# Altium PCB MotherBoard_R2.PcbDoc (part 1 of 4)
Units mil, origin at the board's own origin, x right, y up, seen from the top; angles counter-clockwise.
Board outline 9500 x 4600 mil, 4 copper layers (Top Layer, Power Layer, GND Layer, Bottom Layer), stack 61.6 mil thick; 206 components, 289 nets, 935 pads, 328 vias.
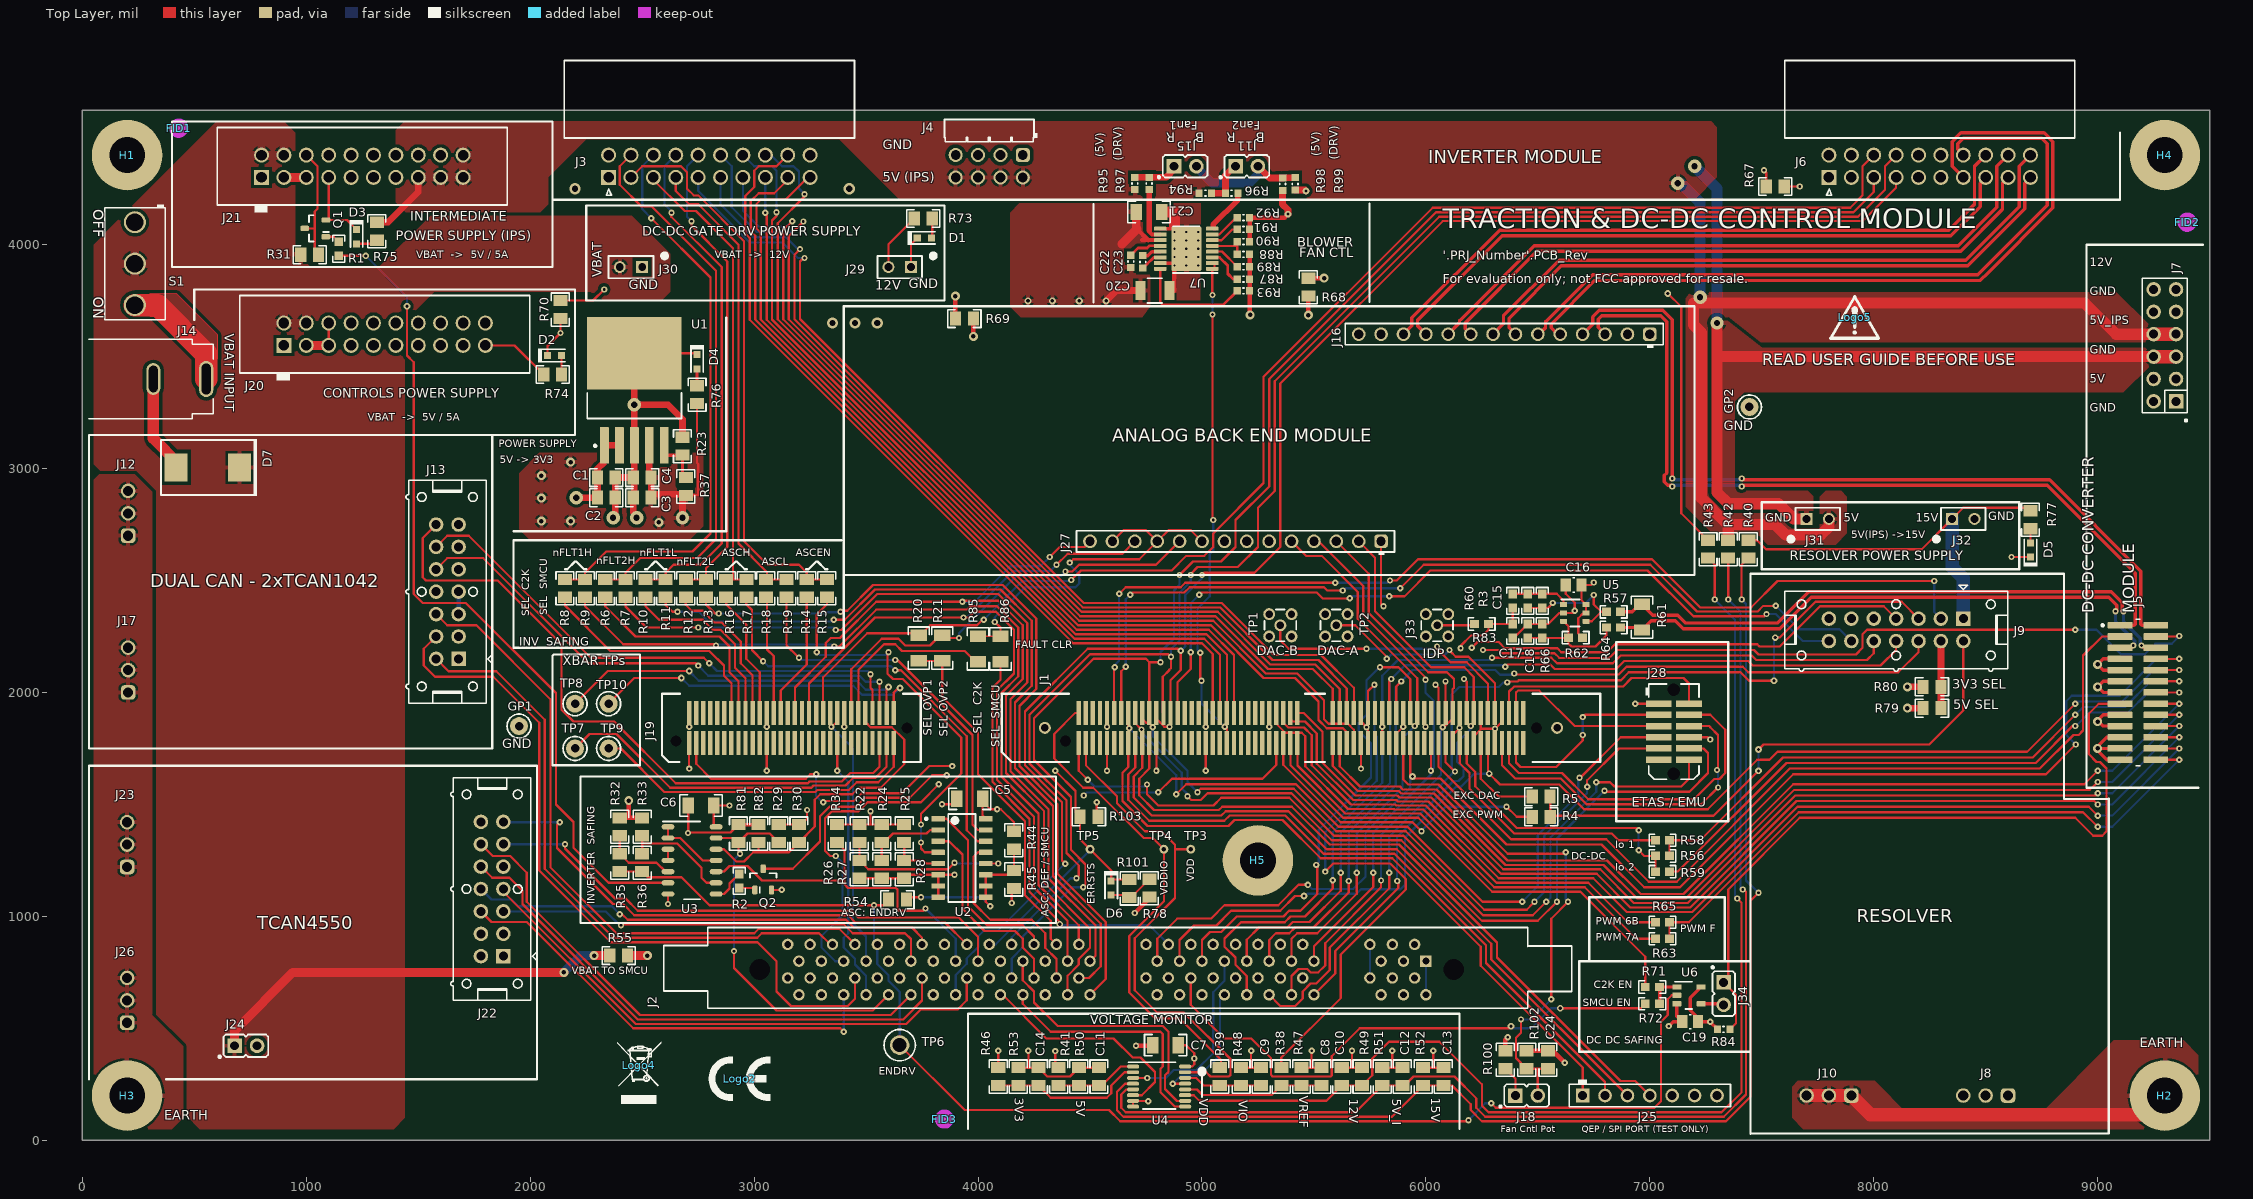
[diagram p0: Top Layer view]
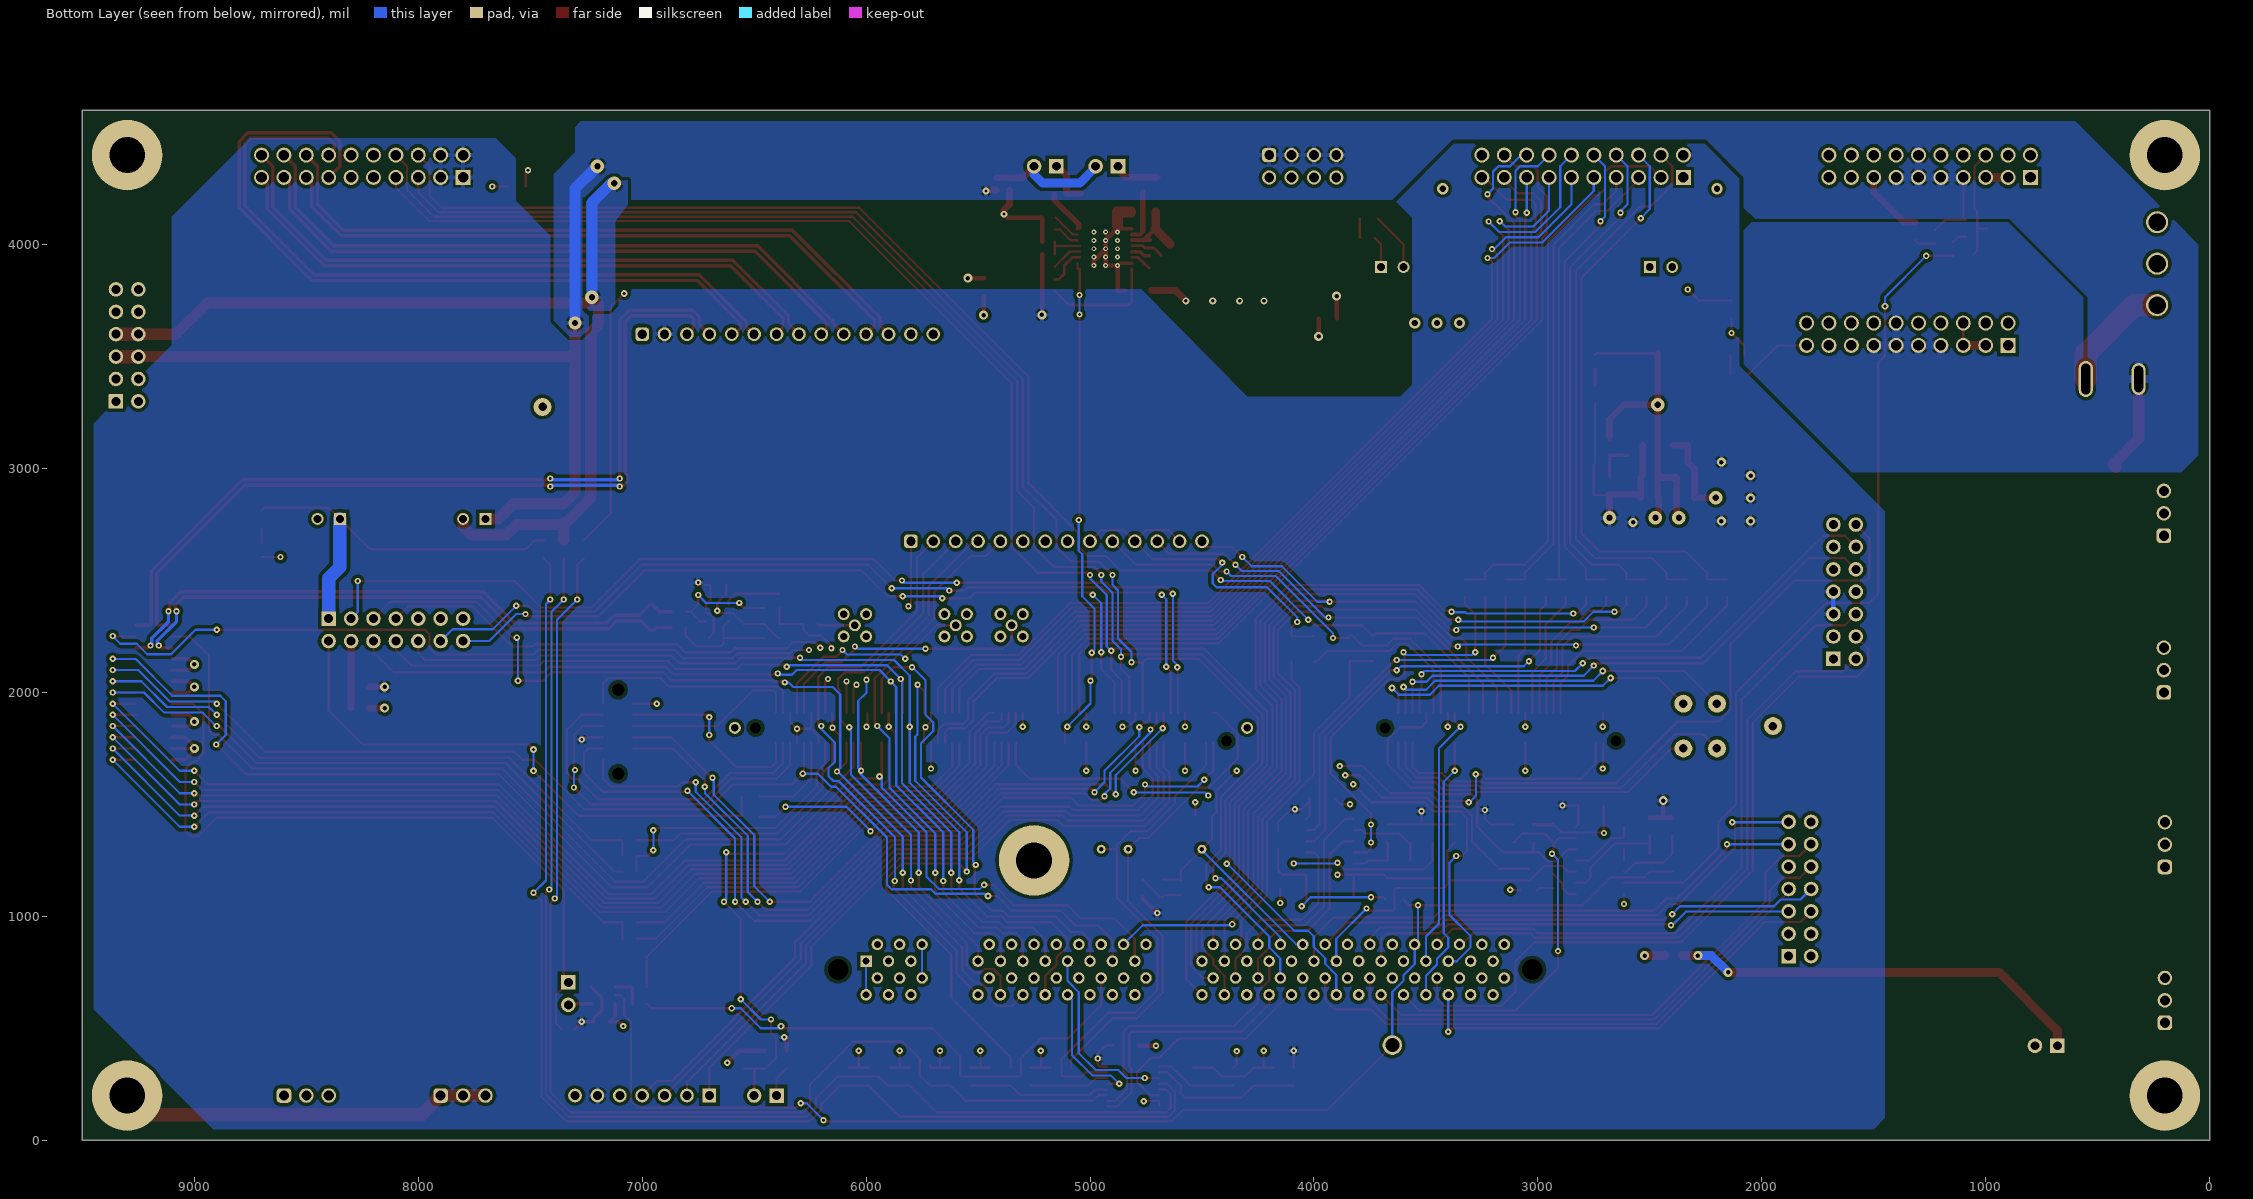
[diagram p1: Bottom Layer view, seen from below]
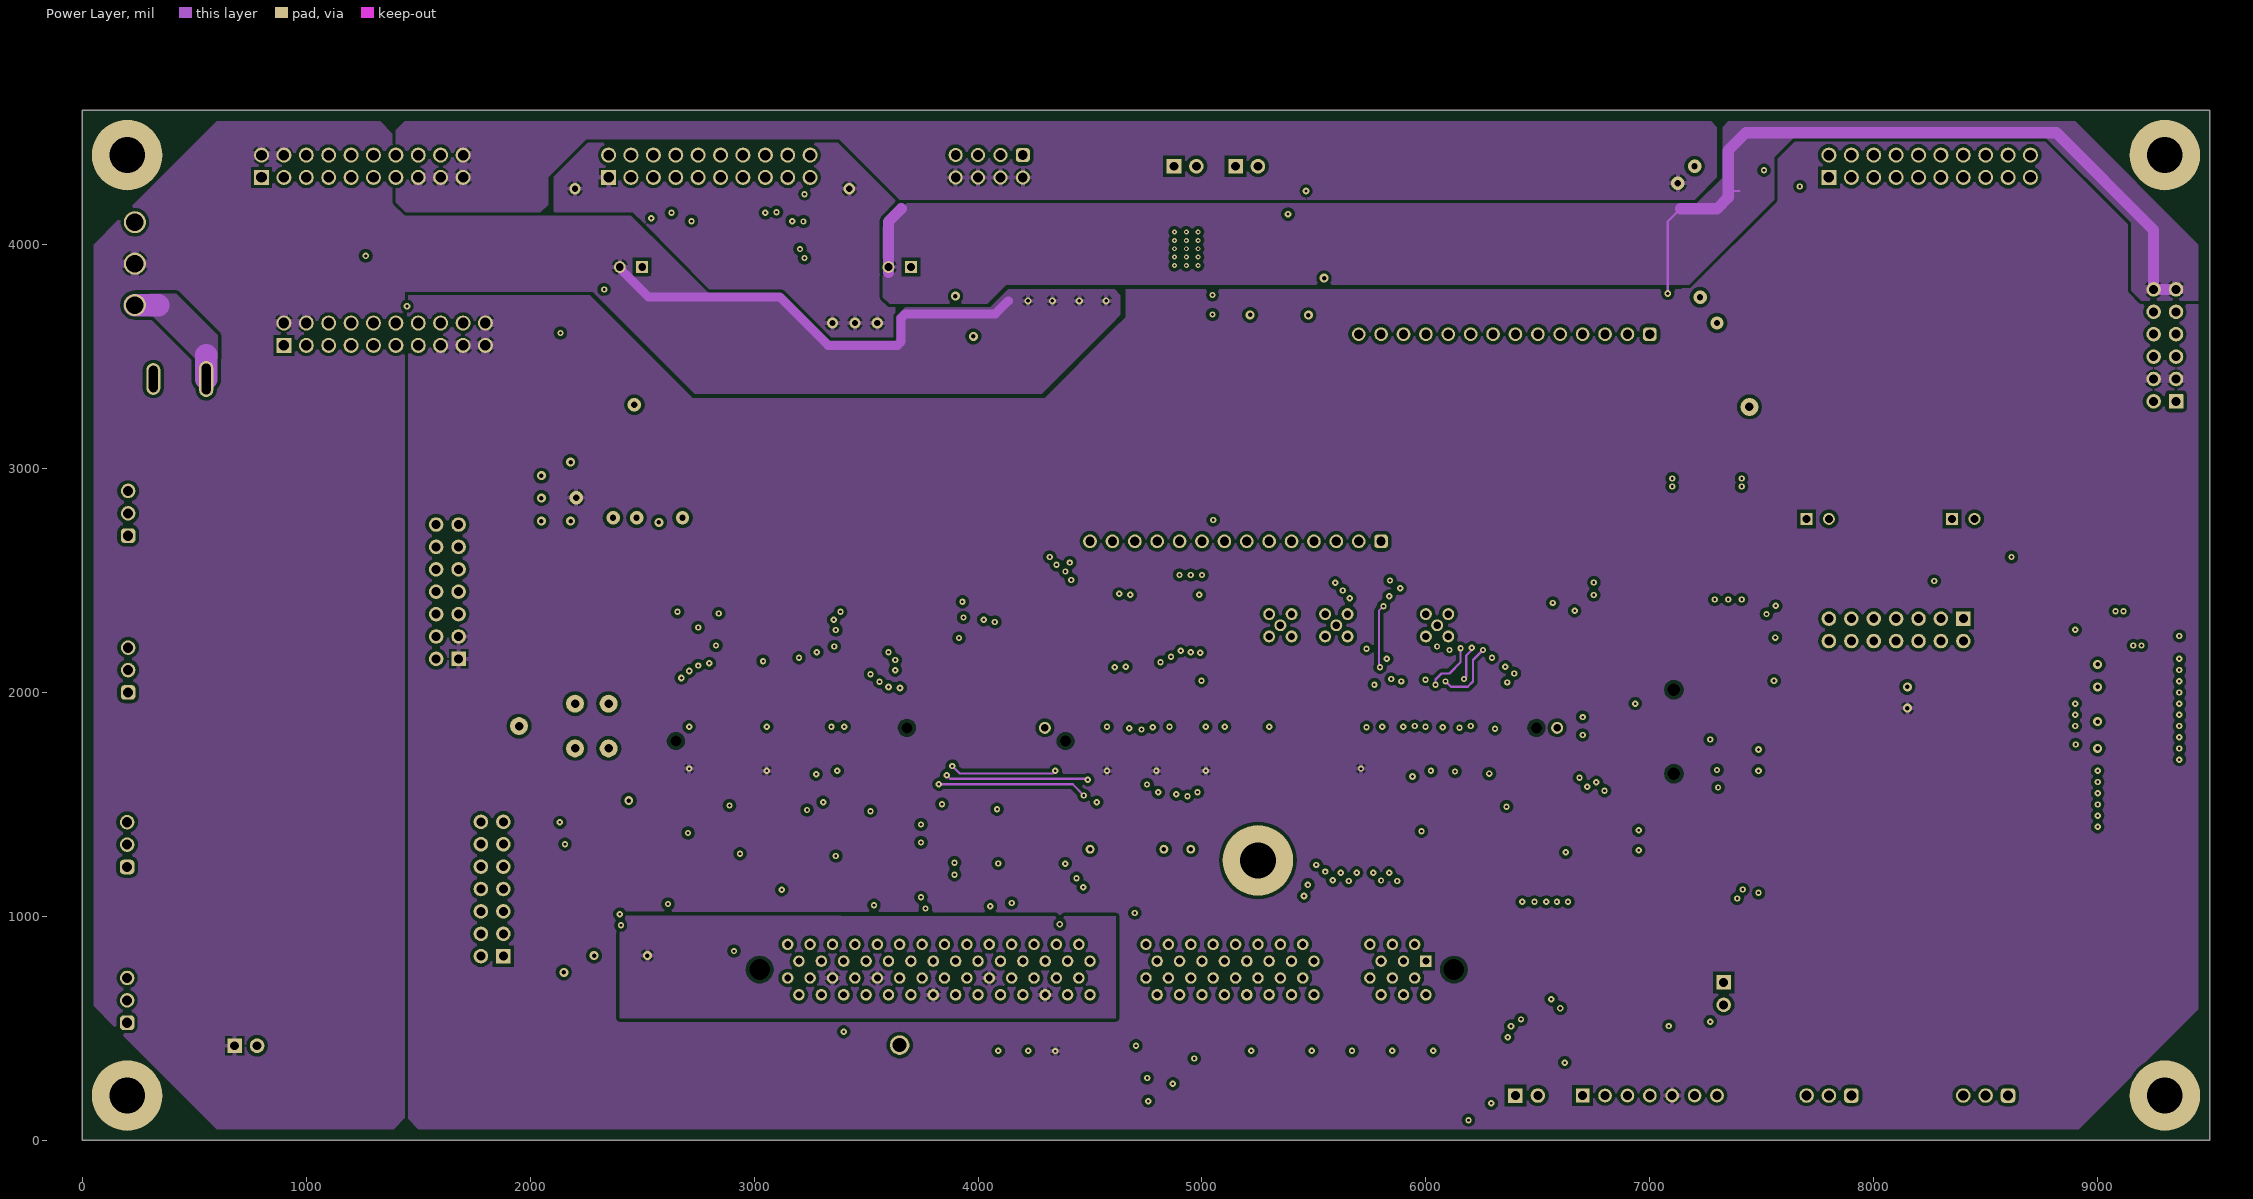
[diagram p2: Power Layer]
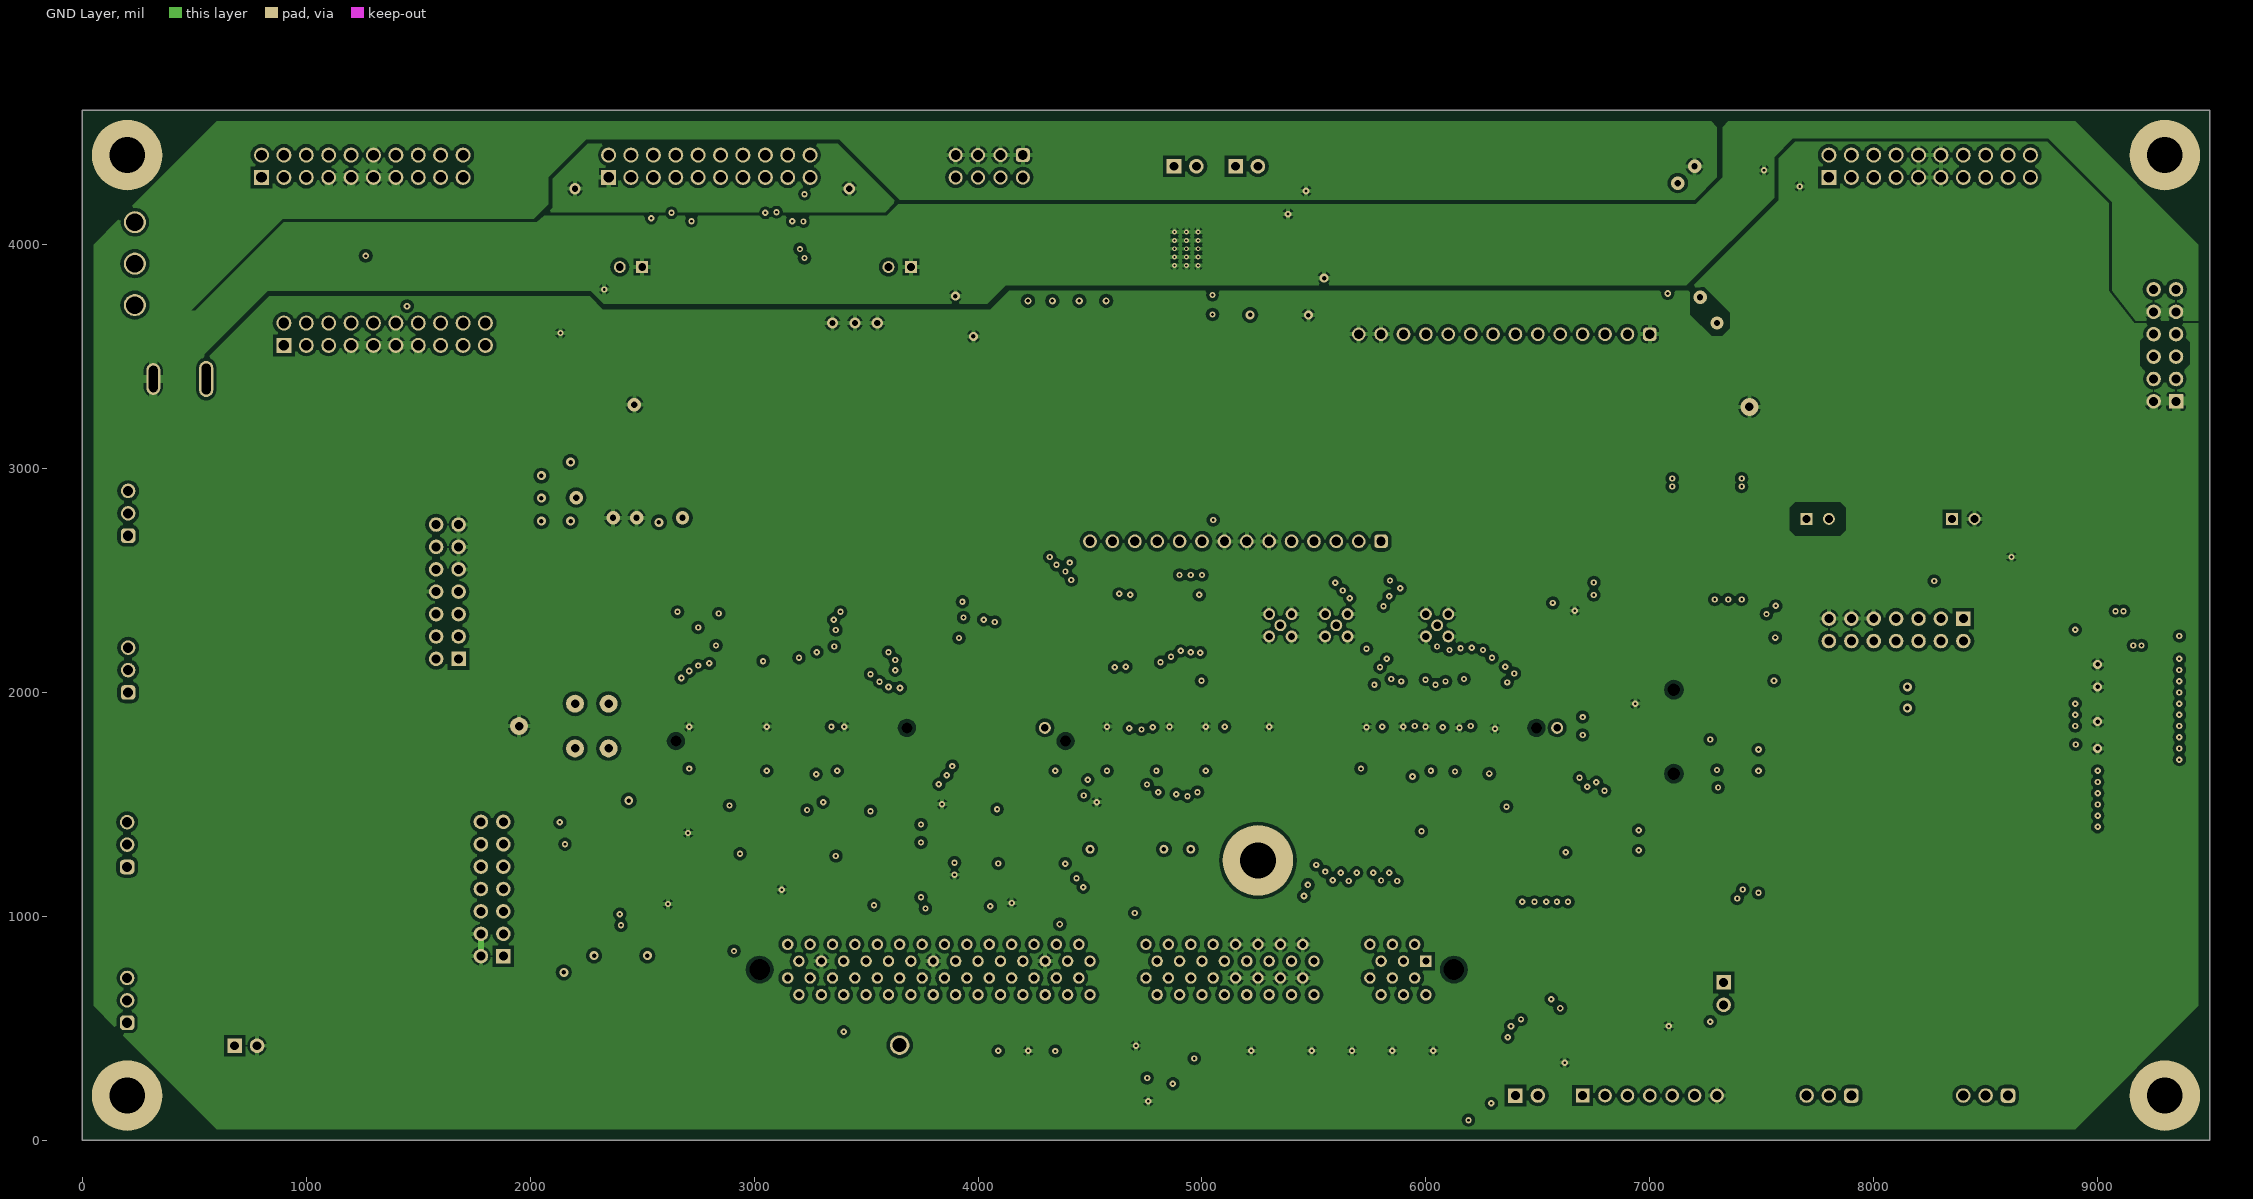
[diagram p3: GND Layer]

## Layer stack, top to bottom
Top Solder: solder mask 0.4, Solder Resist, Dk 3.5
Top Layer: signal copper 1.4
Dielectric 1: prepreg 8, FR-4, Dk 4.2
Power Layer: signal copper 1.4
Dielectric 2: core 40, FR-4, Dk 4.2
GND Layer: signal copper 1.4
Dielectric 3: prepreg 8, FR-4, Dk 4.2
Bottom Layer: signal copper 1.4
Bottom Solder: solder mask 0.4, Solder Resist, Dk 3.5

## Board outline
0,0 9500,0 9500,4600 0,4600

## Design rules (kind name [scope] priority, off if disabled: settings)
AcuteAngle [All] p1: minimum=4.50000000000000E+0001 checktracksonly=FALSE
AssemblyTestPointUsage [All] p1: valid=2
BoardOutlineClearance BoardOutlineClearance_MountingHoles [OnCopper and InComponentClass('Mounting Holes')] p1: gap=39.37 ignorepadtopadclearanceinfootprint=FALSE
BoardOutlineClearance BoardOutlineClearance_Poly [OnCopper and IsPoly] p2: gap=25 ignorepadtopadclearanceinfootprint=FALSE
BoardOutlineClearance [OnCopper and Not InComponentClass('Logo') and not InComponentClass('FiducialMark') and not InRegion(1000,500,4000,800) and not InPoly] p3: gap=75 ignorepadtopadclearanceinfootprint=FALSE
Clearance Clearance_New [HasFootprint('YJM0003A')] p1: gap=6 ignorepadtopadclearanceinfootprint=TRUE
Clearance Clearance_Keepouts [((IsTrack Or IsArc) And Not InPoly) And IsFree and IsKeepOut vs ((IsTrack Or IsArc) And Not InPoly) And IsFree and IsKeepOut] p2: gap=0 ignorepadtopadclearanceinfootprint=FALSE
Clearance Clearance_Poly [InPolygon] p3: gap=15 ignorepadtopadclearanceinfootprint=TRUE
Clearance Clearance_FiducialMark [IsKeepOut and InComponentClass('FiducialMark') vs IsPad and InComponentClass('FiducialMark')] p4: gap=0 ignorepadtopadclearanceinfootprint=FALSE
Clearance [All] p5: gap=7.87 ignorepadtopadclearanceinfootprint=TRUE
ComponentClearance ComponentClearance_MountingHoles_FiducialMarks [InComponentClass('Mounting Holes') vs InComponentClass('FiducialMark')] p1: gap=50 collisioncheckmode=3 verticalgap=10 showdistances=FALSE
ComponentClearance ComponentClearance_Shunt [InComponentClass('Header') vs InComponentClass('Shunt')] p2: gap=0 collisioncheckmode=3 verticalgap=0 showdistances=FALSE
ComponentClearance ComponentClearance_Logo [InComponentClass('Logo')] p3: gap=50 collisioncheckmode=3 verticalgap=10 showdistances=FALSE
ComponentClearance ComponentClearance_ScrewToNut [(HasFootprint('NY PMS 440 0025 PH')) vs (HasFootprint('Keystone_1902C'))] p4: gap=5 collisioncheckmode=3 verticalgap=10 showdistances=FALSE
ComponentClearance ComponentClearance_MountingHoles [InComponentClass('Mounting Holes')] p5: gap=100 collisioncheckmode=3 verticalgap=100000 showdistances=FALSE
ComponentClearance ComponentClearance_SmallPassives [HasFootprint('0201*') or HasFootprint('0402*') or HasFootprint('0508') or HasFootprint('0603*') or HasFootprint('0612') or HasFootprint('0805*') or HasFootprint('0815*') or HasFootprint('0830*') or HasFootprint('1206*') or HasFootprint('1210*') or HasFootprint('1808*') or HasFootprint('1812*') or HasFootprint('1825*') or HasFootprint('2010*') or HasFootprint('2220*') or HasFootprint('2225*') or HasFootprint('2512*') or HasFootprint('2728*') or HasFootprint('3518*') vs HasFootprint('0201*') or HasFootprint('0402*') or HasFootprint('0508') or HasFootprint('0603*') or HasFootprint('0612') or HasFootprint('0805*') or HasFootprint('0815*') or HasFootprint('0830*') or HasFootprint('1206*') or HasFootprint('1210*') or HasFootprint('1808*') or HasFootprint('1812*') or HasFootprint('1825*') or HasFootprint('2010*') or HasFootprint('2220*') or HasFootprint('2225*') or HasFootprint('2512*') or HasFootprint('2728*') or HasFootprint('3518*')] p6: gap=14.96 collisioncheckmode=3 verticalgap=10 showdistances=FALSE
ComponentClearance ComponentClearance_THtoSMT [IsThruComponent vs IsSMTComponent] p7: gap=40 collisioncheckmode=3 verticalgap=30 showdistances=FALSE
ComponentClearance ComponentClearance_THtoTH [IsThruComponent vs IsThruComponent] p8: gap=30 collisioncheckmode=3 verticalgap=30 showdistances=FALSE
ComponentClearance [All] p9: gap=30 collisioncheckmode=3 verticalgap=10 showdistances=FALSE
DiffPairsRouting [All] p1: maxlimit=100 minlimit=10 mostfreqgap=10 toplayer_minwidth=15 toplayer_maxwidth=15 toplayer_prefwidth=15 midlayer1_minwidth=15 midlayer1_maxwidth=15 midlayer1_prefwidth=15 midlayer2_minwidth=15 midlayer2_maxwidth=15 midlayer2_prefwidth=15 bottomlayer_minwidth=15 bottomlayer_maxwidth=15 bottomlayer_prefwidth=15 maxuncoupledlength=1000
FabricationTestPointUsage TestPointUsage [All] p1: valid=2 allowmultiple=FALSE
FabricationTestpoint Testpoint [All] p1: side=3 testpointundercomponent=TRUE minsize=40 maxsize=100 preferedsize=60 minholesize=0 maxholesize=40 preferedholesize=32 testpointgrid=1 allowsidetop=TRUE allowsidebottom=TRUE usegrid=TRUE gridtolerance=0.01
FanoutControl Fanout_LCC [IsLCC] p1: bgadir=Out bgaviamode=Centered fanoutstyle=Auto fanoutdirection=Alternating viagrid=1 // Fanout_LCC (Default Rule)
FanoutControl Fanout_BGA [IsBGA] p2: bgadir=Out bgaviamode=Centered fanoutstyle=Auto fanoutdirection=Alternating viagrid=1 // Fanout_BGA (Default Rule)
FanoutControl Fanout_Default [All] p4: bgadir=Out bgaviamode=Centered fanoutstyle=Auto fanoutdirection=Alternating viagrid=1 // Fanout_Default (Default Rule)
FanoutControl Fanout_Small [(CompPinCount < 5)] p5: bgadir=Out bgaviamode=Centered fanoutstyle=Auto fanoutdirection=OutThenIn viagrid=1 // Fanout_Small (Default Rule)
Height [All] p1: minheight=0 maxheight=2000 prefheight=500
HoleSize [All] p1: absolutevalues=TRUE maxlimit=251 minlimit=7.87 maxpercent=80.000 minpercent=20.000
MinimumAnnularRing MinimumAnnularRing_ThermalPadVias [IsVia and InAnyComponent] p1: minimumring=5.91
MinimumAnnularRing [All] p2: minimumring=7.87
MinimumSolderMaskSliver MinimumSolderMaskSliver_Logo [InComponentClass('Logo') vs InComponentClass('Logo')] p1: minsoldermaskwidth=0.7
MinimumSolderMaskSliver [All] p2: minsoldermaskwidth=3.94
PlaneClearance [All] p1: clearance=12
PlaneConnect [All] p1: planeconnectstyle=Relief reliefexpansion=10 reliefentries=4 reliefconductorwidth=25 reliefairgap=10
PolygonConnect [InComponentClass('PowerTerminal')] p1: connectstyle=Relief reliefconductorwidth=40 reliefentries=4 polygonreliefangle="90 Angle" airgapwidth=10
PolygonConnect PolygonConnect_1 [Not InComponentClass('PowerTerminal')] p2: connectstyle=Relief reliefconductorwidth=20 reliefentries=4 polygonreliefangle="90 Angle" airgapwidth=10
RoutingVias ThermalPadVias [IsVia and InAnyComponent] p1: holewidth=7.87 width=19.68 viastyle="Through Hole" minholewidth=7.87 minwidth=19.68 maxholewidth=12.99 maxwidth=23.62
RoutingVias [All] p2: holewidth=16 width=34 viastyle="Through Hole" minholewidth=7.87 minwidth=26 maxholewidth=40 maxwidth=65
SilkToBoardRegionClearance [Not ((IsComment or IsDesignator) And (Hide <> 'False')) and not InRegion(1000,500,4000,800)] p1:
SilkToSilkClearance SilkToSilkClearance_Pb-FreeLogo [(HasFootprint('Pb-Free_Overlay_Medium') OR HasFootprint('Pb-Free_Overlay_Small')) vs (HasFootprint('Pb-Free_Overlay_Medium') OR HasFootprint('Pb-Free_Overlay_Small'))] p1: silktosilkclearance=0
SilkToSilkClearance [All] p2: silktosilkclearance=3.94
SilkToSolderMaskClearance SilkToComponentPadClearance [(IsPad or IsFill or IsRegion) and InAnycomponent] p1: minsilkscreentomaskgap=5 clearancetoexposedcopper=TRUE
SilkToSolderMaskClearance "Silk to Solder Mask Opening" [All] p2: minsilkscreentomaskgap=3.94 clearancetoexposedcopper=FALSE
SolderMaskExpansion [All] p1: expansion=1.97
UnRoutedNet [All] p1: checkbadconnections=TRUE
Width [All] p1: maxlimit=100 minlimit=6 preferedwidth=10 checkconnectedcopper=TRUE
12 further rules are at their usual default settings.

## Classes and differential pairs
component class PowerTerminal: J7 J14 J20 J21 S1
component class ChildBoardDC-DC_r2: C15 C16 C17 C18 C19 J5 J7 J33 J34 R3 R56 R57 R58 R59 R60 R61 R62 R63 R64 R65 R66 R71 R72 R83 R84 U5 U6
component class MotherBoard_r2: d GP1 GP2 J1 J2 J19 TP1 TP2 TP3 TP4 TP5 TP6 TP7 TP8 TP9 TP10
component class powerSupplyAndMontior_r1: C1 C2 C3 C4 C6 C7 C8 C9 C10 C11 C12 C13 C14 D1 D2 D3 D4 D5 D6 D7 J14 J20 J21 J29 J30 J31 J32 Q1 Q2 R1 R2 R23 R29 R30 R31 R32 R33 R34 R35 R36 R37 R38 R39 R40 R41 R42 R43 R46 R47 R48 R49 R50 R51 R52 R53 R55 R67 R68 R69 R70 R73 R74 R75 R76 R77 R78 R81 R82 R101 R103 S1 U1 U3 U4
component class ChildBoardMotor_r2: C5 C20 C21 C22 C23 C24 J3 J4 J6 J8 J9 J10 J11 J15 J16 J18 J25 J27 R4 R5 R6 R7 R8 R9 R10 R11 R12 R13 R14 R15 R16 R17 R18 R19 R20 R21 R22 R24 R25 R26 R27 R28 R44 R45 R54 R79 R80 R85 R86 R87 R88 R89 R90 R91 R92 R93 R94 R95 R96 R97 R98 R99 R100 R102 U2 U7
component class ChildBoardComms_r3: J12 J13 J17 J22 J23 J24 J26 J28
component class Header: J4 J8 J10 J11 J12 J15 J17 J18 J23 J24 J26 J29 J30 J31 J32 J34
component class "Mounting Holes": H1 H2 H3 H4 H5
component class Hardware: FID1 FID2 FID3 H1 H2 H3 H4 H5 Logo2 Logo3 Logo4 Logo5 ZZ1 ZZ2 ZZ3 ZZ4
component class FiducialMark: FID1 FID2 FID3
component class AssemblyNote: ZZ1 ZZ2 ZZ3 ZZ4
differential pair CT: +CT_P -CT_N
differential pair Vdc2: +Vdc2_P -Vdc2_N
differential pair Ia: +Ia_P -Ia_N
differential pair Vdc: +Vdc_P -Vdc_N
differential pair Ic: +Ic_P -Ic_N
differential pair Ib: +Ib_P -Ib_N

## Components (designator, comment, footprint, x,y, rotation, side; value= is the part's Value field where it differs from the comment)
C1 "C2012X7R2A104K125AA" 0805_HV 2340,2960 r0 top value=0.1uF
C2 "GRM21BR61C106KE15K" 0805_HV 2340,2870 r0 top value=10uF
C3 "GRM21BR61C106KE15K" 0805_HV 2500,2870 r0 top value=10uF
C4 "C2012X7R2A104K125AA" 0805_HV 2500,2960 r180 top value=0.1uF
C5 "1206YC104KAT2A" 1206 3962.91,1525 r180 top value=0.1uF
C6 "1206YC104KAT2A" 1206 2762.91,1495 r0 top value=0.1uF
C7 "1206YC104KAT2A" 1206 4837.91,425 r180 top value=0.1uF
C8 "GRM21BR61C106KE15K" 0805_HV 5534.41,284.57 r270 top value=10uF
C9 "GRM21BR61C106KE15K" 0805_HV 5264.41,284.57 r270 top value=10uF
C10 "GRM21BR61C106KE15K" 0805_HV 5624.41,284.57 r270 top value=10uF
C11 "GRM21BR61C106KE15K" 0805_HV 4540,284.57 r270 top value=10uF
C12 "GRM21BR61C106KE15K" 0805_HV 5895,284.57 r270 top value=10uF
C13 "GRM21BR61C106KE15K" 0805_HV 6077.8,284.57 r270 top value=10uF
C14 "GRM21BR61C106KE15K" 0805_HV 4270,284.57 r270 top value=10uF
C15 "GCM188R71H224KA64D" 0603 6520,2408.9 r270 top value=0.22uF
C16 "CEU4J2X7R1H104K125AE" 0805_150 6660,2480 r180 top value=0.1uF
C17 "GCM188R71H224KA64D" 0603 6388.23,2274.5 r270 top value=0.22uF
C18 "GCM188R71H224KA64D" 0603 6455,2274.5 r90 top value=0.22uF
C19 "CEU4J2X7R1H104K125AE" 0805_150 7180,530 r180 top value=0.1uF
C20 "UMJ325KB7106MMHP" 1210_280 4790,3795 r0 top value=10uF
C21 "GRM319R71H104KA01D" 1206 4763.63,4146.03 r0 top value=0.1uF
C22 "885012206095" 0603L 4682.3,3925 r90 top value=0.1uF
C23 "885012206091" 0603L 4736,3923 r270 top value=0.022uF
C24 "SR0805X7R104K1NT95(F)#M123A" 0805_HV 6545,360 r270 top value=0.1uF
D1 "150060GS75000" WL-SMCW_GREEN 3760,4030 r0 top value=Green
D2 "150060GS75000" WL-SMCW_GREEN 2108.5,3505 r0 top value=Green
D3 "150060GS75000" WL-SMCW_GREEN 1225,4035.2 r270 top value=Green
D4 "150060GS75000" WL-SMCW_GREEN 2745,3476.86 r270 top value=Green
D5 "150060GS75000" WL-SMCW_GREEN 8700,2636.5 r90 top value=Green
D6 "150060RS75000" WL-SMCW_RED 4594.67,1127 r270 top value=Red
D7 "S10AL-TP" SMC_265 560,3005 r180 top value=50V
FID1 "Fiducial" Fiducial10-20 430.84,4520 r0 top
FID2 "Fiducial" Fiducial10-20 9400,4100 r0 top
FID3 "Fiducial" Fiducial10-20 3850,95 r0 top
GP1 "TESTPOINT" TESTPOINT 1950,1850 r0 top
GP2 "TESTPOINT" TESTPOINT 7445,3275 r0 top
H1 "NY PMS 440 0025 PH" "NY PMS 440 0025 PH"#1 200,4400 r0 top locked
H2 "NY PMS 440 0025 PH" "NY PMS 440 0025 PH"#1 9300,200 r0 top locked
H3 "NY PMS 440 0025 PH" "NY PMS 440 0025 PH"#2 200,225 r0 top locked
H4 "NY PMS 440 0025 PH" "NY PMS 440 0025 PH"#1 9300,4400 r0 top locked
H5 "NY PMS 440 0025 PH" "NY PMS 440 0025 PH"#3 5250,1240 r0 top locked
J1 "HSEC8-160-01-L-DV-A-BL" controlCARD-120HSEC 5514.69,1842.8 r180 top
J2 "TMDSDIM100CON5PK" TI_TMDSDIM100CON5PK 4623.7,767.4 r180 top
J3 "SBH11-PBPC-D10-RA-BK" Sullins_SBH11-xxxC-D10-RA 2800,4555.12 r90 top
J4 "61300821021" Wurth_61300821021 4050,4350 r270 top
J5 "FTSH-113-01-F-DV-K" FP-FTSH-113-01-F-DV-K_HDR26-MFG 9180.12,2000 r270 top
J6 "SBH11-PBPC-D10-RA-BK" Sullins_SBH11-xxxC-D10-RA 8250,4555.12 r90 top
J7 "TSW-106-07-G-D" TSW-106-07-G-D 9300,3550 r90 top
J8 "61300311121" WURTH_61300311121 8499.66,200 r180 top
J9 "SBH11-PBPC-D07-ST-BK" CONN_SBH11-PBPC-D07-ST-BK 8100,2279.7 r180 top
J10 "61300311121" WURTH_61300311121 7800,200 r180 top
J11 "PBC02SAAN" Sullins_PBC02SAAN 5200,4350 r90 top
J12 "61300311121" WURTH_61300311121 204.36,2800.01 r90 top
J13 "SBH11-PBPC-D07-ST-BK" CONN_SBH11-PBPC-D07-ST-BK 1629.98,2450 r90 top
J14 "PJ-037AH" CUI_PJ-037AH 435,3400 r270 top
J15 "PBC02SAAN" Sullins_PBC02SAAN 4925,4350 r90 top
J16 "SSW-114-01-G-S" Samtec_SSW-114-01-x-S 6350,3600 r180 top
J17 "61300311121" WURTH_61300311121 204.36,2100 r90 top
J18 "PBC02SAAN" Sullins_PBC02SAAN 6450,200 r90 top
J19 "HSEC8-130-01-L-DV-A" controlCARD-180HSEC-60pinAddon 3166.31,1841.93 r180 top
J20 "SBH11-PBPC-D10-ST-BK" Sullins_SBH11-xxxC-D10-ST 1350,3600 r90 top
J21 "SBH11-PBPC-D10-ST-BK" Sullins_SBH11-xxxC-D10-ST 1250,4350 r90 top
J22 "SBH11-PBPC-D07-ST-BK" CONN_SBH11-PBPC-D07-ST-BK 1829.98,1122.3 r90 top
J23 "61300311121" WURTH_61300311121 200,1320.59 r90 top
J24 "PBC02SAAN" Sullins_PBC02SAAN 729.98,422.3 r90 top
J25 "PPPC071LFBN-RC" Sullins_xPxC071LFBN 7000,200 r0 top
J26 "61300311121" WURTH_61300311121 200,625 r90 top
J27 "SSW-114-01-G-S" Samtec_SSW-114-01-x-S 5150,2675 r180 top
J28 "TFM-106-02-S-D-A" Samtec_TFM-106-02-x-D-A 7107.48,1825 r0 top
J29 "5-534206-1" CONN_534206-1 3650,3900 r180 top
J30 "5-534206-1" CONN_534206-1 2450,3900 r180 top
J31 "5-534206-1" CONN_534206-1 7750,2775 r0 top
J32 "5-534206-1" CONN_534206-1 8400,2775 r0 top
J33 "734151471" Molex_0734151471 6050,2300 r0 top
J34 "PBC02SAAN" Sullins_PBC02SAAN 7330,655 r0 top
Logo2 "CE Mark" CE_Mark_5mm 2935,275 r0 top
Logo3 "FCC disclaimer" FCC_disclaimer 12010,4440 r0 top
Logo4 "WEEE logo" WEEE_Minimum 2485,335 r0 top
Logo5 "CAUTION.  READ USER GUIDE BEFORE USE" IEC_Caution_Small 7915,3675 r0 top
Q1 "DMN3053L-7" SOT-23 1040.1,4072.6 r180 top value=30V
Q2 "DMN3053L-7" SOT-23 3040.4,1165.24 r90 top value=30V
R1 "CRCW0603100RFKEA" 0603 1145,3981.5 r270 top value=100
R2 "CRCW0603100RFKEA" 0603 2933,1158.5 r90 top value=100
R3 "RC0603FR-071KL" 0603 6455,2408.9 r90 top value=1.00k
R4 "ERJ-6GEY0R00V" 0805_HV 6515,1444.5 r0 top value=0
R5 "ERJ-6GEY0R00V" 0805_HV 6514.76,1535 r0 top value=0
R6 "ERJ-6GEY0R00V" 0805_HV 2335,2465 r90 top value=0
R7 "ERJ-6GEY0R00V" 0805_HV 2425,2465 r270 top value=0
R8 "ERJ-6GEY0R00V" 0805_HV 2155,2465 r90 top value=0
R9 "ERJ-6GEY0R00V" 0805_HV 2245,2465 r270 top value=0
R10 "ERJ-6GEY0R00V" 0805_HV 2515,2465 r90 top value=0
R11 "ERJ-6GEY0R00V" 0805_HV 2605,2465 r270 top value=0
R12 "ERJ-6GEY0R00V" 0805_HV 2695,2465 r90 top value=0
R13 "ERJ-6GEY0R00V" 0805_HV 2785,2465 r270 top value=0
R14 "ERJ-6GEY0R00V" 0805_HV 3235,2465 r90 top value=0
R15 "ERJ-6GEY0R00V" 0805_HV 3325,2465 r270 top value=0
R16 "ERJ-6GEY0R00V" 0805_HV 2875,2465 r90 top value=0
R17 "ERJ-6GEY0R00V" 0805_HV 2965,2465 r270 top value=0
R18 "ERJ-6GEY0R00V" 0805_HV 3052.6,2465 r90 top value=0
R19 "ERJ-6GEY0R00V" 0805_HV 3145,2465 r270 top value=0
R20 "RCA12060000ZSEA" 1206 3735,2197.91 r90 top value=0
R21 "RCA12060000ZSEA" 1206 3840,2197.91 r90 top value=0
R22 "ERJ-6GEY0R00V" 0805_HV 3470,1370 r90 top value=0
R23 "ERJ-P06F1001V" 0805_HV 2680,3100 r270 top value=1.00k
R24 "ERJ-6GEY0R00V" 0805_HV 3570,1370 r90 top value=0
R25 "ERJ-6GEY0R00V" 0805_HV 3670,1370 r90 top value=0
R26 "ERJ-6GEY0R00V" 0805_HV 3470,1210 r90 top value=0
R27 "ERJ-6GEY0R00V" 0805_HV 3570,1210 r90 top value=0
R28 "ERJ-6GEY0R00V" 0805_HV 3670,1210 r90 top value=0
R29 "RT0805BRD07100KL" 0805_HV 3110,1370 r90 top value=100k
R30 "RT0805BRD07100KL" 0805_HV 3200,1370 r90 top value=100k
R31 "ERJ-6GEYJ203V" 0805_HV 1015,3955 r180 top value=20k
R32 "ERJ-6GEY0R00V" 0805_HV 2400,1400 r90 top value=0
R33 "ERJ-6GEY0R00V" 0805_HV 2500,1400 r90 top value=0
R34 "RT0805BRD07100KL" 0805_HV 3370,1370 r90 top value=100k
R35 "ERJ-6GEY0R00V" 0805_HV 2400,1240 r90 top value=0
R36 "ERJ-6GEY0R00V" 0805_HV 2500,1240 r90 top value=0
R37 "ERJ-6ENF1691V" 0805_HV 2695,2920 r90 top value=1.69k
R38 "RR1220P-562-D" 0805_HV 5354.41,284.57 r90 top value=5.60k
R39 "RR1220P-3741-D-M" 0805_HV 5079.41,284.57 r90 top value=3.74k
R40 "ERJ-6ENF9091V" 0805_HV 7440,2640 r90 top value=9.09k
R41 "ERJ-6ENF6191V" 0805_HV 4360,284.57 r90 top value=6.19k
R42 "RR1220P-4531-D-M" 0805_HV 7350,2640 r90 top value=4.53k
R43 "ERJ-6ENF9091V" 0805_HV 7260,2640 r90 top value=9.09k
R44 "ERJ-6GEYJ203V" 0805_HV 4160,1340 r90 top value=20k
R45 "ERJ-6GEYJ203V" 0805_HV 4160,1165 r90 top value=20k
R46 "RR1220P-3741-D-M" 0805_HV 4090,284.57 r90 top value=3.74k
R47 "ERJ-P06F1001V" 0805_HV 5444.41,284.57 r270 top value=1.00k
R48 "ERJ-P06F1001V" 0805_HV 5174.41,284.57 r270 top value=1.00k
R49 "ERJ-P06F1001V" 0805_HV 5714.41,284.57 r270 top value=1.00k
R50 "ERJ-P06F1001V" 0805_HV 4450,284.57 r270 top value=1.00k
R51 "ERJ-P06F1001V" 0805_HV 5805,284.57 r270 top value=1.00k
R52 "ERJ-P06F1001V" 0805_HV 5987.8,284.57 r270 top value=1.00k
R53 "ERJ-P06F1001V" 0805_HV 4180,284.57 r270 top value=1.00k
R54 "ERJ-6GEY0R00V" 0805_HV 3640,1075 r180 top value=0
R55 "ERJ-6GEY0R00V" 0805_HV 2395,825 r0 top value=0
R56 "RCS06030000Z0EA" 0603 7056.5,1270 r180 top value=0
R57 "RC0603FR-071KL" 0603 6838.01,2360 r180 top value=1.00k
R58 "RCS06030000Z0EA" 0603 7056.5,1340 r180 top value=0
R59 "RCS06030000Z0EA" 0603 7056.5,1200 r180 top value=0
R60 "CRCW060310R0FKEAHP" 0603 6388.23,2408.9 r270 top value=10.0
R61 "CRCW12065R36FKEA" 1206 6965,2336 r90 top value=5.36
R62 "ERJ-3EKF2202V" 0603 6668.5,2245 r0 top value=22.0k
R63 "RCS06030000Z0EA" 0603 7056.5,900 r180 top value=0
R64 "RC0603FR-071KL" 0603 6838.01,2290 r180 top value=1.00k
R65 "RCS06030000Z0EA" 0603 7056.5,974 r180 top value=0
R66 "RC0603FR-071K05L" 0603 6520,2274.5 r270 top value=1.05k
R67 "ERJ-6GEY0R00V" 0805_HV 7560,4259.64 r0 top value=0
R68 "ERJ-6GEY0R00V" 0805_HV 5475,3810 r90 top value=0
R69 "ERJ-6GEY0R00V" 0805_HV 3939.07,3670 r180 top value=0
R70 "ERJ-6GEY0R00V" 0805_HV 2134.8,3710 r90 top value=0
R71 "RCS06030000Z0EA" 0603 7011.5,684.8 r0 top value=0
R72 "RCS06030000Z0EA" 0603 7011.5,610 r0 top value=0
R73 "ERJ-6ENF1212V" 0805_HV 3755,4116.75 r180 top value=12.1k
R74 "ERJ-6ENF4991V" 0805_HV 2100,3420 r180 top value=4.99k
R75 "ERJ-6ENF4991V" 0805_HV 1315,4060 r90 top value=4.99k
R76 "ERJ-6ENF3401V" 0805_HV 2745,3330 r270 top value=3.40k
R77 "CRCW080515K0FKEA" 0805_HV 8700,2771.32 r90 top value=15.0k
R78 "ERJ-6ENF3401V" 0805_HV 4765,1126 r270 top value=3.40k
R79 "ERJ-6GEY0R00V" 0805_HV 8260,1930 r0 top value=0
R80 "ERJ-6GEY0R00V" 0805_HV 8260,2025 r0 top value=0
R81 "RR1220P-103-D" 0805_HV 2930.09,1370 r270 top value=10.0k
R82 "RR1220P-103-D" 0805_HV 3020,1370 r270 top value=10.0k
R83 "RC0603FR-0749R9L" 0603 6248.5,2306 r180 top value=49.9
R84 "ERA-3ARW103V" 0603L 7330,495 r180 top value=10.0k
R85 "RCA12060000ZSEA" 1206 4000,2194.85 r90 top value=0
R86 "RCA12060000ZSEA" 1206 4100,2194.85 r90 top value=0
R87 "ERA-3ARW103V" 0603L 5185,3846.03 r180 top value=10.0k
R88 "ERA-3ARW103V" 0603L 5185,3956.03 r0 top value=10.0k
R89 "ERA-3ARW103V" 0603L 5185,3901.03 r180 top value=10.0k
R90 "ERA-3ARW103V" 0603L 5185,4013.15 r180 top value=10.0k
R91 "CRCW06031K50JNEA" 0603L 5185,4067.92 r180 top value=1.5k
R92 "ERJ-3GEY0R00V" 0603L 5185,4121.03 r180 top value=0
R93 "ERA-3ARW103V" 0603L 5185,3793.59 r180 top value=10.0k
R94 "ERJ-3GEY0R00V" 0603L 5015,4229.87 r0 top value=0
R95 "ERJ-3GEY0R00V" 0603L 4700,4272.85 r90 top value=0
R96 "ERJ-3GEY0R00V" 0603L 5132.48,4230 r180 top value=0
R97 "ERJ-3GEY0R00V" 0603L 4764,4272.85 r90 top value=0
R98 "ERJ-3GEY0R00V" 0603L 5360,4270.26 r90 top value=0
R99 "ERJ-3GEY0R00V" 0603L 5416.01,4271.73 r90 top value=0
R100 "CRCW0805100RFKEA" 0805_HV 6355,360 r90 top value=100
R101 "CRCW080515K0FKEA" 0805_HV 4675,1125 r270 top value=15.0k
R102 "CRCW0805100RFKEA" 0805_HV 6450,360 r270 top value=100
R103 "ERJ-P06F1001V" 0805_HV 4495,1445 r0 top value=1.00k
S1 "100SP3T1B1M3QEH" SW_100SP3T1B1M3QEH 234.52,3915.04 r270 top
TP1 "734151471" Molex_0734151471 5350,2300 r0 top
TP2 "734151471" Molex_0734151471 5600,2300 r0 top
TP3 "TP_H0.45P0.75" TP_H045P075 4950,1300 r0 top
TP4 "TP_H0.45P0.75" TP_H045P075 4830,1300 r0 top
TP5 "TP_H0.45P0.75" TP_H045P075 4500,1300 r0 top
TP6 "5008" Keystone5008 3650,425 r0 top
TP7 "TESTPOINT" TESTPOINT 2200,1750 r0 top
TP8 "TESTPOINT" TESTPOINT 2200,1950 r0 top
TP9 "TESTPOINT" TESTPOINT 2350,1750 r0 top
TP10 "TESTPOINT" TESTPOINT 2350,1950 r0 top
U1 "TL1963AQKTTRQ1" KTT0005A_N 2465,3349.65 r90 top
U2 "CD4053BQM96Q1" D0016A-MFG 3928,1261 r0 top
U3 "SN74HC00QDRG4Q1" D0014A_N 2722.72,1250 r0 top
U4 "SN74LV4052AQPWRQ1" PW0016A_N 4808.42,240 r0 top
U5 "OPA836IDBVR" DBV0006A_L 6665,2355 r0 top
U6 "SN74AHC1G08QDBVRQ1" DBV0005A_N 7174.87,647.4 r0 top
U7 "DRV8876QPWPRQ1" PWP0016J_N 4930,3981.63 r180 top
ZZ1 "This Assembly Note is for PCB labels only" AssemblyNoteLabel 30,7360 r0 top
ZZ2 "These assemblies are ESD sensitive, ESD precautions shall be observed." AssemblyNote 20,7250 r0 top
ZZ3 "These assemblies must be clean and free from flux and all contaminants. Use of no clean flux is not acceptable." AssemblyNote 20,7160 r0 top
ZZ4 "These assemblies must comply with workmanship standards IPC-A-610 Class 2, unless otherwise specified." AssemblyNote 20,7070 r0 top

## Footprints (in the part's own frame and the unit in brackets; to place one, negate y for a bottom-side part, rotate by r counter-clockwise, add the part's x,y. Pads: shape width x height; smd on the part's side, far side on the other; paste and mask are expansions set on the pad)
0603 [mm] "0603 from SM-752 data"
  rect 1x0.95 smd: 1(-0.8,0) 2(0.8,0)
  silkscreen extent -1.52,-0.69 1.52,0.69, body extent -0.87,-0.47 0.87,0.47, height 1
0603L [mm] "0603 from SM-752 data"
  rect 0.8x0.85 smd: 1(-0.7,0) 2(0.7,0)
  silkscreen extent -0.07,-0.33 0.07,0.33, body extent -0.87,-0.47 0.87,0.47, height 1
0805_150 [mm] "0805 / 1.5 mm height"
  rect 1.15x1.45 smd: 1(-0.9,0) 2(0.9,0)
  silkscreen extent -0.1,-0.8 0.1,0.8, body extent -1.1,-0.72 1.1,0.72, height 1.5
0805_HV [mil] "0805 with 30mil clearance between pads"
  rect 50x63 smd: 1(-40,0) 2(40,0)
  silkscreen extent -74,-40 74,40, body extent -43,-29 43,29, height 57
1206 [mm] "1206 from SM-752 data"
  rect 1.3x1.85 smd: 1(-1.45,0) 2(1.45,0)
  silkscreen extent -2.4,-1.21 2.4,1.21, body extent -1.7,-0.9 1.7,0.9, height 1.35
1210_280 [mm] "SMD, 2-Leads, Body 3.6x2.8mm, Height 2.8mm"
  rect 1.1x2.2 smd: 1(-1.65,0) 2(1.65,0)
  silkscreen extent -0.84,-1.4 0.84,1.4, body extent -1.8,-1.4 1.8,1.4, height 2.8
AssemblyNote [mil] "Assembly Note"
AssemblyNoteLabel [mil] "Assembly Note for PCB Labels"
CE_Mark_5mm [mil] "Minimum text height for CE Mark"
  silkscreen extent -138,-98 138,98
CONN_534206-1 [mm] "TE_CONNECTIVITY"
  rect 1.35x1.35 hole 0.89: 1(-1.27,0)
  round 1.35 hole 0.89: 2(1.27,0)
  silkscreen extent -4.06,-1.52 2.54,1.27, body extent -2.51,-1.27 2.51,1.27, height 8.65
CONN_SBH11-PBPC-D07-ST-BK [mm] "Sullins recommended land pattern"
  rect 1.65x1.65 hole 1.016 mask+0: 1(-7.62,-1.27)
  round 1.65 hole 1.016 mask+0: 2(-7.62,1.27) 3(-5.08,-1.27) 4(-5.08,1.27) 5(-2.54,-1.27) 6(-2.54,1.27) 7(0,-1.27) 8(0,1.27) 9(2.54,-1.27) 10(2.54,1.27) 11(5.08,-1.27) 12(5.08,1.27) 13(7.62,-1.27) 14(7.62,1.27)
  silkscreen extent -12.64,-5.08 12.64,4.7, body extent -12.64,-4.4 12.64,4.7, height 9.12
controlCARD-120HSEC [mm] "Pads are not numbered according to Samtec datasheet."
  rect 0.5x2.724 smd: 1(-23.357,-1.678) 2(-23.357,1.722) 3(-22.557,-1.678) 4(-22.557,1.722) 5(-21.757,-1.678) 6(-21.757,1.722) 7(-20.957,-1.678) 8(-20.957,1.722) 9(-20.157,-1.678) 10(-20.157,1.722) 11(-19.357,-1.678) 12(-19.357,1.722) 13(-18.557,-1.678) 14(-18.557,1.722) 15(-17.757,-1.678) 16(-17.757,1.722) 17(-16.957,-1.678) 18(-16.957,1.722) 19(-16.157,-1.678) 20(-16.157,1.722) 21(-15.357,-1.678) 22(-15.357,1.722) 23(-14.557,-1.678) 24(-14.557,1.722) 25(-13.757,-1.678) 26(-13.757,1.722) 27(-12.957,-1.678) 28(-12.957,1.722) 29(-12.157,-1.678) 30(-12.157,1.722) 31(-11.357,-1.678) 32(-11.357,1.722) 33(-10.557,-1.678) 34(-10.557,1.722) 35(-9.757,-1.678) 36(-9.757,1.722) 37(-8.957,-1.678) 38(-8.957,1.722) 39(-8.157,-1.678) 40(-8.157,1.722) 41(-7.357,-1.678) 42(-7.357,1.722) 43(-6.557,-1.678) 44(-6.557,1.722) 45(-5.757,-1.678) 46(-5.757,1.722) 47(-4.957,-1.678) 48(-4.957,1.722) 49(-4.157,-1.678) 50(-4.157,1.722) 51(-3.357,-1.678) 52(-3.357,1.722) 53(-2.557,-1.678) 54(-2.557,1.722) 55(-1.757,-1.678) 56(-1.757,1.722) 57(2.243,-1.678) 58(2.243,1.722) 59(3.043,-1.678) 60(3.043,1.722) 61(3.843,-1.678) 62(3.843,1.722) 63(4.643,-1.678) 64(4.643,1.722) 65(5.443,-1.678) 66(5.443,1.722) 67(6.243,-1.678) 68(6.243,1.722) 69(7.043,-1.678) 70(7.043,1.722) 71(7.843,-1.678) 72(7.843,1.722) 73(8.643,-1.678) 74(8.643,1.722) 75(9.443,-1.678) 76(9.443,1.722) 77(10.243,-1.678) 78(10.243,1.722) 79(11.043,-1.678) 80(11.043,1.722) 81(11.843,-1.678) 82(11.843,1.722) 83(12.643,-1.678) 84(12.643,1.722) 85(13.443,-1.678) 86(13.443,1.722) 87(14.243,-1.678) 88(14.243,1.722) 89(15.043,-1.678) 90(15.043,1.722) 91(15.843,-1.678) 92(15.843,1.722) 93(16.643,-1.678) 94(16.643,1.722) 95(17.443,-1.678) 96(17.443,1.722) 97(18.243,-1.678) 98(18.243,1.722) 99(19.043,-1.678) 100(19.043,1.722) 101(19.843,-1.678) 102(19.843,1.722) 103(20.643,-1.678) 104(20.643,1.722) 105(21.443,-1.678) 106(21.443,1.722) 107(22.243,-1.678) 108(22.243,1.722) 109(23.043,-1.678) 110(23.043,1.722) 111(23.843,-1.678) 112(23.843,1.722) 113(24.643,-1.678) 114(24.643,1.722) 115(25.443,-1.678) 116(25.443,1.722) 117(26.243,-1.678) 118(26.243,1.722) 119(27.043,-1.678) 120(27.043,1.722)
  round 0.025 hole 1.27 unplated mask+0.876: 181(-24.857,0.022) 182(28.543,1.522)
  round 1.348 hole 0.84: 185(-27.207,0.022) 186(30.893,0.022)
  silkscreen extent -32.11,-3.86 35.8,3.9, body extent -31.75,-3.48 35.3,3.52, height 12.35
controlCARD-180HSEC-60pinAddon [mm] "Pads are not numbered according to datasheet."
  round 0.025 hole 1.27 unplated mask+0.876: 61(-13.1,0) 62(13.1,1.5)
  rect 0.5x2.724 smd: 121(-11.6,-1.7) 122(-11.6,1.7) 123(-10.8,-1.7) 124(-10.8,1.7) 125(-10,-1.7) 126(-10,1.7) 127(-9.2,-1.7) 128(-9.2,1.7) 129(-8.4,-1.7) 130(-8.4,1.7) 131(-7.6,-1.7) 132(-7.6,1.7) 133(-6.8,-1.7) 134(-6.8,1.7) 135(-6,-1.7) 136(-6,1.7) 137(-5.2,-1.7) 138(-5.2,1.7) 139(-4.4,-1.7) 140(-4.4,1.7) 141(-3.6,-1.7) 142(-3.6,1.7) 143(-2.8,-1.7) 144(-2.8,1.7) 145(-2,-1.7) 146(-2,1.7) 147(-1.2,-1.7) 148(-1.2,1.7) 149(-0.4,-1.7) 150(-0.4,1.7) 151(0.4,-1.7) 152(0.4,1.7) 153(1.2,-1.7) 154(1.2,1.7) 155(2,-1.7) 156(2,1.7) 157(2.8,-1.7) 158(2.8,1.7) 159(3.6,-1.7) 160(3.6,1.7) 161(4.4,-1.7) 162(4.4,1.7) 163(5.2,-1.7) 164(5.2,1.7) 165(6,-1.7) 166(6,1.7) 167(6.8,-1.7) 168(6.8,1.7) 169(7.6,-1.7) 170(7.6,1.7) 171(8.4,-1.7) 172(8.4,1.7) 173(9.2,-1.7) 174(9.2,1.7) 175(10,-1.7) 176(10,1.7) 177(10.8,-1.7) 178(10.8,1.7) 179(11.6,-1.7) 180(11.6,1.7)
  silkscreen extent -14.68,-3.88 14.68,3.88, body extent -14.3,-3.5 14.3,3.5, height 7.95
CUI_PJ-037AH [mm] "Power Jack, 2mm, R/A, TH"
  oval 4.1x1.6 hole 1 slot 3.5 at 0 deg: 1(0,3)
  oval 3.6x1.6 hole 1 slot 3 at 0 deg: 2(0,-3)
  silkscreen extent -4.5,-10.3 4.5,3.8, body extent -4.5,-10.7 4.5,3.8, height 11
D0014A_N [mm] "SOIC, 14-Leads, Body 8.7x3.9mm, Pitch 1.27mm, IPC Medium Density"
  oval 1.45x0.6 smd: 1(-2.725,3.81) 2(-2.725,2.54) 3(-2.725,1.27) 4(-2.725,0) 5(-2.725,-1.27) 6(-2.725,-2.54) 7(-2.725,-3.81) 8(2.725,-3.81) 9(2.725,-2.54) 10(2.725,-1.27) 11(2.725,0) 12(2.725,1.27) 13(2.725,2.54) 14(2.725,3.81)
  silkscreen extent -3.3,-4.4 0.9,4.4, body extent -3.02,-4.32 3.02,4.32, height 1.6
D0016A-MFG [mm]
  rrect17% 1.55x0.6 smd paste-1000 mask+0: 1(-2.7,4.445) 2(-2.7,3.175) 3(-2.7,1.905) 4(-2.7,0.635) 5(-2.7,-0.635) 6(-2.7,-1.905) 7(-2.7,-3.175) 8(-2.7,-4.445) 9(2.7,-4.445) 10(2.7,-3.175) 11(2.7,-1.905) 12(2.7,-0.635) 13(2.7,0.635) 14(2.7,1.905) 15(2.7,3.175) 16(2.7,4.445)
  silkscreen extent -4.17,-5 1.55,5, body extent -3.57,-5.25 3.57,5.25, height 0.25
DBV0005A_N [mm] "SOT23, 5-Leads, Body 2.9x1.6mm, Pitch 0.95mm, Lead Span 2.8mm, IPC Medium Density"
  rrect17% 1x0.6 smd: 1(-1.375,0.95) 2(-1.375,0) 3(-1.375,-0.95) 4(1.375,-0.95) 5(1.375,0.95)
  silkscreen extent -1.63,-1.55 0.38,1.55, body extent -1.42,-1.46 1.42,1.46, height 1.09
DBV0006A_L [mm] "SOT23, 6-Leads, Body 2.9x1.6mm, Pitch 0.95mm, Lead Span 2.8mm, IPC High Density"
  rrect18% 0.8x0.55 smd: 1(-1.275,0.95) 2(-1.275,0) 3(-1.275,-0.95) 4(1.275,-0.95) 5(1.275,0) 6(1.275,0.95)
  silkscreen extent -1.55,-1.53 0.55,1.53, body extent -1.42,-1.46 1.42,1.46, height 1.12
FCC_disclaimer [mil]
Fiducial10-20 [mm]
  round 1 smd mask+0.5: 1(0,0)
  Top Layer keep-out circle w1.178: c0,0 r0.5
FP-FTSH-113-01-F-DV-K_HDR26-MFG [mm] "Header, 2.54mm, 13x2, TH"
  rrect14% 0.74x2.79 smd paste+0 mask+0: 1(-7.62,-2.035) 2(-7.62,2.035) 3(-6.35,-2.035) 4(-6.35,2.035) 5(-5.08,-2.035) 6(-5.08,2.035) 7(-3.81,-2.035) 8(-3.81,2.035) 9(-2.54,-2.035) 10(-2.54,2.035) 11(-1.27,-2.035) 12(-1.27,2.035) 13(0,-2.035) 14(0,2.035) 15(1.27,-2.035) 16(1.27,2.035) 17(2.54,-2.035) 18(2.54,2.035) 19(3.81,-2.035) 20(3.81,2.035) 21(5.08,-2.035) 22(5.08,2.035) 23(6.35,-2.035) 24(6.35,2.035) 25(7.62,-2.035) 26(7.62,2.035)
  silkscreen extent -8.32,-4.14 8.32,0.27, body extent -8.42,-3.53 8.42,3.53, height 0.25
IEC_Caution_Small [mil]
  silkscreen extent -107,-93 107,92
Keystone5008 [mil] "Keystone Compact loops"
  round 87 hole 63: 1(0,0)
  silkscreen extent -70,-70 70,70, body extent -63,-63 62,63, height 225
KTT0005A_N [mm] "D2-PAK, 6-Leads, Body 8.9x10.2mm, Pitch 1.7mm, Lead Span 15.2mm, IPC Medium Density"
  rrect10% 4.15x1 smd: 1(-6.25,3.4) 2(-6.25,1.7) 3(-6.25,0) 4(-6.25,-1.7) 5(-6.25,-3.4)
  rrect1% 8.2x10.75 smd: 6(4.2,0)
  silkscreen extent -6.42,-5.35 -0.3,5.35, body extent -7.63,-5.08 7.63,5.08, height 4.83
Molex_0734151471 [mm] "MMCX JACK, Gold, TH"
  round 1.35 hole 0.84: 1(0,0) 2(-1.27,1.27) 3(1.27,1.27) 4(1.27,-1.27) 5(-1.27,-1.27)
  silkscreen extent -1.8,-1.8 1.8,1.8, body extent -1.76,-1.76 1.76,1.76, height 4.42
"NY PMS 440 0025 PH"#1 [mm] "4-40 nylon screw and mounting hole"
  round 8 hole 4.064: 1(0,0)
  body extent -3.3,-3.3 3.3,3.3, height 2.69
"NY PMS 440 0025 PH"#2 [mm] "4-40 nylon screw and mounting hole"
  round 8 hole 4.064: 1(0,-0.635)
  body extent -3.3,-3.3 3.3,3.3, height 2.69
"NY PMS 440 0025 PH"#3 [mm] "4-40 nylon screw and mounting hole"
  round 8 hole 4.064: 1(0,0.254)
  body extent -3.3,-3.3 3.3,3.3, height 2.69
PW0016A_N [mm] "TSOP, 16-Leads, Body 5x4.4mm, Pitch 0.65mm, IPC Medium Density"
  oval 1.4x0.45 smd: 1(-2.95,2.275) 2(-2.95,1.625) 3(-2.95,0.975) 4(-2.95,0.325) 5(-2.95,-0.325) 6(-2.95,-0.975) 7(-2.95,-1.625) 8(-2.95,-2.275) 9(2.95,-2.275) 10(2.95,-1.625) 11(2.95,-0.975) 12(2.95,-0.325) 13(2.95,0.325) 14(2.95,0.975) 15(2.95,1.625) 16(2.95,2.275)
  silkscreen extent -3.5,-2.55 1.85,2.75, body extent -3.21,-2.5 3.21,2.5, height 1
PWP0016J_N [mm] "TSOP, 16-Leads, Body 5x4.4mm, Pitch 0.65mm, Exposed Pad, IPC Medium Density"
  rrect22% 1.4x0.45 smd: 1(-2.95,2.275) 2(-2.95,1.625) 3(-2.95,0.975) 4(-2.95,0.325) 5(-2.95,-0.325) 6(-2.95,-0.975) 7(-2.95,-1.625) 8(-2.95,-2.275) 9(2.95,-2.275) 10(2.95,-1.625) 11(2.95,-0.975) 12(2.95,-0.325) 13(2.95,0.325) 14(2.95,0.975) 15(2.95,1.625) 16(2.95,2.275)
  rrect6% 3.4x5 smd paste-1.7 mask-1.7: 17(0,0)
  rrect4% 2.46x3.55 on Top Paste: 17(0,0)
  rrect4% 2.46x3.55 on Top Solder: 17(0,0)
  silkscreen extent -3.55,-2.55 1.5,2.75, body extent -3.2,-2.5 3.2,2.5, height 1.13
Samtec_SSW-114-01-x-S [mm] "Receptacle, 2.54mm, 14x1, TH"
  rrect50% 1.55x1.55 hole 1.04: 1(-16.51,0)
  round 1.55 hole 1.04: 2(-13.97,0) 3(-11.43,0) 4(-8.89,0) 5(-6.35,0) 6(-3.81,0) 7(-1.27,0) 8(1.27,0) 9(3.81,0) 10(6.35,0) 11(8.89,0) 12(11.43,0) 13(13.97,0) 14(16.51,0)
  silkscreen extent -18.03,-1.21 18.03,1.57, body extent -18.03,-1.21 18.03,1.21, height 8.51
Samtec_TFM-106-02-x-D-A [mm] "Header(Shrouded), 1.27mm, 6x2, SMT"
  rect 2.92x0.74 smd: 1(-1.715,3.175) 2(1.715,3.175) 3(-1.715,1.905) 4(1.715,1.905) 5(-1.715,0.635) 6(1.715,0.635) 7(-1.715,-0.635) 8(1.715,-0.635) 9(-1.715,-1.905) 10(1.715,-1.905) 11(-1.715,-3.175) 12(1.715,-3.175)
  round 1 hole 1.42 unplated: MH1(0,4.765) MH2(0,-4.765)
  silkscreen extent -3.2,-5.4 2.86,5.4, body extent -2.98,-5.4 2.98,5.4, height 5.74
SMC_265 [mm] "SMD, 2-Leads, Body 7.15x6.25mm"
  rect 2.6x3.2 smd: 1(-3.6,0) 2(3.6,0)
  silkscreen extent -5.6,-3.23 5.3,3.22, body extent -4.07,-3.13 4.07,3.13, height 2.65
SOT-23 [mm] "SOT23, 3-Leads, Body 2.9x1.3mm, Pitch 0.95mm, Lead Span 2.5mm, IPC Medium Density"
  rrect50% 1x0.6 smd: 1(-1.2,0.95) 2(-1.2,-0.95) 3(1.2,0)
  silkscreen extent -1.62,-1.5 0.7,1.5, body extent -1.16,-1.45 1.21,1.45, height 1
Sullins_PBC02SAAN [mm] "Sullins 100mil, 1x2, 230 mil above insulator"
  rect 1.65x1.65 hole 1.016: 1(0,1.27)
  round 1.65 hole 1.016: 2(0,-1.27)
  silkscreen extent -1.37,-2.54 1.27,3.1, body extent -1.27,-2.54 1.27,2.54, height 8.38
Sullins_SBH11-xxxC-D10-RA [mm] "Header(Shrouded), 2.54mm, 10x2, TH"
  rect 1.7x1.7 hole 1.2: 1(-6.48,11.43)
  round 1.7 hole 1.2: 2(-3.94,11.43) 3(-6.48,8.89) 4(-3.94,8.89) 5(-6.48,6.35) 6(-3.94,6.35) 7(-6.48,3.81) 8(-3.94,3.81) 9(-6.48,1.27) 10(-3.94,1.27) 11(-6.48,-1.27) 12(-3.94,-1.27) 13(-6.48,-3.81) 14(-3.94,-3.81) 15(-6.48,-6.35) 16(-3.94,-6.35) 17(-6.48,-8.89) 18(-3.94,-8.89) 19(-6.48,-11.43) 20(-3.94,-11.43)
  silkscreen extent -8.5,-16.45 6.8,16.45, body extent -6.8,-16.45 6.8,16.45, height 9.1
Sullins_SBH11-xxxC-D10-ST [mm] "Header (Shrouded), 2.54mm, 10x2, TH"
  rect 1.7x1.7 hole 1.2: 1(-1.27,11.43)
  round 1.7 hole 1.2: 2(1.27,11.43) 3(-1.27,8.89) 4(1.27,8.89) 5(-1.27,6.35) 6(1.27,6.35) 7(-1.27,3.81) 8(1.27,3.81) 9(-1.27,1.27) 10(1.27,1.27) 11(-1.27,-1.27) 12(1.27,-1.27) 13(-1.27,-3.81) 14(1.27,-3.81) 15(-1.27,-6.35) 16(1.27,-6.35) 17(-1.27,-8.89) 18(1.27,-8.89) 19(-1.27,-11.43) 20(1.27,-11.43)
  silkscreen extent -5.25,-16.45 4.4,16.45, body extent -4.4,-16.45 4.7,16.45, height 9.11
Sullins_xPxC071LFBN [mm] "Receptacle, 2.54mm, 7x1, TH"
  rect 1.55x1.55 hole 1.02: 1(-7.62,0)
  round 1.55 hole 1.02: 2(-5.08,0) 3(-2.54,0) 4(0,0) 5(2.54,0) 6(5.08,0) 7(7.62,0)
  silkscreen extent -9.14,-1.27 9.14,1.8, body extent -9.14,-1.27 9.14,1.27, height 8.5
SW_100SP3T1B1M3QEH [mm] "TH, Body 12.7x6.86mm, Pitch 4.7mm"
  round 2.5 hole 2: 1(-4.7,0) 2(0,0) 3(4.7,0)
  silkscreen extent -6.7,-3.43 6.35,3.43, body extent -6.35,-3.43 6.35,3.43, height 28.19
TESTPOINT [mil]
  round 80 hole 37.99: 1(0,0)
  silkscreen extent -54,-53 54,53
TI_TMDSDIM100CON5PK [mm] "Texas Instruments"
  rect 1.3x1.3 hole 0.787: 1(-34.958,-0.828)
  round 1.3 hole 0.787: 2(-33.688,-2.733) 3(-32.418,-0.828) 4(-31.148,-2.733) 5(-29.878,-0.828) 6(-28.608,-2.733) 7(-22.258,-0.828) 8(-20.988,-2.733) 9(-19.718,-0.828) 10(-18.448,-2.733) 11(-17.178,-0.828) 12(-15.908,-2.733) 13(-14.638,-0.828) 14(-13.368,-2.733) 15(-12.098,-0.828) 16(-10.828,-2.733) 17(-9.558,-0.828) 18(-8.288,-2.733) 19(-7.018,-0.828) 20(-5.748,-2.733) 21(-4.478,-0.828) 22(-3.208,-2.733) 23(3.142,-0.828) 24(4.412,-2.733) 25(5.682,-0.828) 26(6.952,-2.733) 27(8.222,-0.828) 28(9.492,-2.733) 29(10.762,-0.828) 30(12.032,-2.733) 31(13.302,-0.828) 32(14.572,-2.733) 33(15.842,-0.828) 34(17.112,-2.733) 35(18.382,-0.828) 36(19.652,-2.733) 37(20.922,-0.828) 38(22.192,-2.733) 39(23.462,-0.828) 40(24.732,-2.733) 41(26.002,-0.828) 42(27.272,-2.733) 43(28.542,-0.828) 44(29.812,-2.733) 45(31.082,-0.828) 46(32.352,-2.733) 47(33.622,-0.828) 48(34.892,-2.733) 49(36.162,-0.828) 50(37.432,-2.733) 51(-34.958,2.982) 52(-33.688,1.077) 53(-32.418,2.982) 54(-31.148,1.077) 55(-29.878,2.982) 56(-28.608,1.077) 57(-22.258,2.982) 58(-20.988,1.077) 59(-19.718,2.982) 60(-18.448,1.077) 61(-17.178,2.982) 62(-15.908,1.077) 63(-14.638,2.982) 64(-13.368,1.077) 65(-12.098,2.982) 66(-10.828,1.077) 67(-9.558,2.982) 68(-8.288,1.077) 69(-7.018,2.982) 70(-5.748,1.077) 71(-4.478,2.982) 72(-3.208,1.077) 73(3.142,2.982) 74(4.412,1.077) 75(5.682,2.982) 76(6.952,1.077) 77(8.222,2.982) 78(9.492,1.077) 79(10.762,2.982) 80(12.032,1.077) 81(13.302,2.982) 82(14.572,1.077) 83(15.842,2.982) 84(17.112,1.077) 85(18.382,2.982) 86(19.652,1.077) 87(20.922,2.982) 88(22.192,1.077) 89(23.462,2.982) 90(24.732,1.077) 91(26.002,2.982) 92(27.272,1.077) 93(28.542,2.982) 94(29.812,1.077) 95(31.082,2.982) 96(32.352,1.077) 97(33.622,2.982) 98(34.892,1.077) 99(36.162,2.982) 100(37.432,1.077)
  round 1 hole 2.36 unplated: MH1(-38.128,0.127) MH2(40.612,0.127)
  silkscreen extent -51.5,-4.65 51.5,4.5, body extent -51.4,-4.66 51.4,4.5, height 24.69
TP_H045P075 [mil] "TP_H0.45P0.75"
  round 40 hole 20: 1(0,0)
TSW-106-07-G-D [mm] "Samtec 100mil, 2x6, 230 mil above insulator"
  rrect6% 1.65x1.65 hole 1.016: 1(-6.35,-1.27)
  round 1.65 hole 1.016: 2(-6.35,1.27) 3(-3.81,-1.27) 4(-3.81,1.27) 5(-1.27,-1.27) 6(-1.27,1.27) 7(1.27,-1.27) 8(1.27,1.27) 9(3.81,-1.27) 10(3.81,1.27) 11(6.35,-1.27) 12(6.35,1.27)
  silkscreen extent -8.64,-2.54 7.62,2.54, body extent -7.62,-2.54 7.62,2.54, height 8.38
WEEE_Minimum [mil] "WEEElie bin"
  silkscreen extent -95,-172 99,104
WL-SMCW_GREEN [mm] "WURTH"
  rect 0.8x0.8 smd: 1(-0.8,0) 2(0.8,0)
  silkscreen extent -1.9,-0.8 1.2,0.8, body extent -0.85,-0.45 0.85,0.45, height 0.8
WL-SMCW_RED [mm] "WURTH"
  rect 0.8x0.8 smd: 1(-0.8,0) 2(0.8,0)
  silkscreen extent -1.9,-0.8 1.2,0.8, body extent -0.85,-0.45 0.85,0.45, height 0.8
WURTH_61300311121 [mm] "Header, 2.54mm, 3x1, TH"
  rrect50% 1.65x1.65 hole 1.15: 1(-2.54,0)
  round 1.65 hole 1.15: 2(0,0) 3(2.54,0)
  body extent -3.81,-1.27 3.81,1.27, height 8.54
Wurth_61300821021 [mm] "Header, 2.54mm, 4x2, R/A, TH"
  rrect50% 1.6x1.6 hole 1.1: 1(-1.27,3.81)
  round 1.6 hole 1.1: 2(1.27,3.81) 3(-1.27,1.27) 4(1.27,1.27) 5(-1.27,-1.27) 6(1.27,-1.27) 7(-1.27,-3.81) 8(1.27,-3.81)
  silkscreen extent -5.31,-5.08 -2.77,5.49, body extent -11.31,-5.08 1.59,5.08, height 5.08

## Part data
C1 C4: library part CMP-0007886-2, "CAP, CERM, 0.1 uF, 100 V, +/- 10%, X7R, 0805", Cap_Case=0805, Manufacturer=TDK, Supplier Part Number 1=445-1418-1-ND, TempCo=X7R, Tolerance_%=10%, Value1="0.020726 ohm", Value2=100V, ValueDisplayed=0.1uF
C2 C3 C8 C9 C10 C11 C12 C13 C14: library part CMP-0086228-1, "CAP, CERM, 10 µF, 16 V,+/- 10%, X5R, 0805", Cap_Case=0805, Manufacturer=MuRata, Supplier Part Number 1=490-6473-1-ND, TempCo=X5R, Tolerance_%=10%, Value2=16V, ValueDisplayed=10µF
C5 C6 C7: library part CMP-0860522-1, "CAP, CERM, 0.1 µF, 16 V,+/- 10%, X7R, 1206", Cap_Case=1206, Manufacturer=AVX, TempCo=X7R, Tolerance_%=10%, Value2=16V, ValueDisplayed=0.1µF
C15 C17 C18: library part CMP-0007145-4, "CAP, CERM, 0.22 uF, 50 V, +/- 10%, X7R, AEC-Q200 Grade 1, 0603", Cap_Case=0603, Manufacturer=MuRata, Supplier Part Number 1=490-5402-1-ND, TempCo=X7R, Tolerance_%=10%, Value1=Unknown, Value2=50V, ValueDisplayed=0.22uF
C16 C19: library part CMP-0007961-2, "CAP, CERM, 0.1 uF, 50 V, +/- 10%, X7R, AEC-Q200 Grade 1, 0805", Cap_Case=0805, Manufacturer=TDK, Supplier Part Number 1=445-7856-1-ND, TempCo=X7R, Tolerance_%=10%, Value1=Unknown, Value2=50V, ValueDisplayed=0.1uF
C20: library part CMP-0082302-1, "CAP, CERM, 10 µF, 50 V,+/- 20%, X7R, AEC-Q200 Grade 1, 1210", Cap_Case=1210, Manufacturer="Taiyo Yuden", Supplier Part Number 1=587-6027-1-ND, TempCo=X7R, Tolerance_%=20%, Value2=50V, ValueDisplayed=10µF
C21: library part CMP-0008876-1, "CAP, CERM, 0.1 uF, 50 V, +/- 10%, X7R, 1206", Cap_Case=1206, Manufacturer=MuRata, Supplier Part Number 1=490-1775-1-ND, TempCo=X7R, Tolerance_%=10%, Value1="0.01 ohm", Value2=50V, ValueDisplayed=0.1uF
C22: library part CMP-0006837-4, "CAP, CERM, 0.1 uF, 50 V, +/- 10%, X7R, 0603", Cap_Case=0603, Manufacturer="Wurth Elektronik", TempCo=X7R, Tolerance_%=10%, Value1=Unknown, Value2=50V, ValueDisplayed=0.1uF
C23: library part CMP-0006836-4, "CAP, CERM, 0.022 uF, 50 V, +/- 10%, X7R, 0603", Cap_Case=0603, Manufacturer="Wurth Elektronik", TempCo=X7R, Tolerance_%=10%, Value1=Unknown, Value2=50V, ValueDisplayed=0.022uF
C24: library part CMP-0079722-1, "CAP, CERM, 0.1 µF, 25 V,+/- 10%, X7R, 0805", Cap_Case=0805, Manufacturer="Presidio Components", TempCo=X7R, Tolerance_%=10%, Value2=25V, ValueDisplayed=0.1µF
D1 D2 D3 D4 D5: library part CMP-0002905-2, "LED, Green, SMD", Color=Green, Manufacturer="Wurth Elektronik", Value1=W, Value2=3.2V
D6: library part CMP-0002947-3, "LED, Red, SMD", Color=Red, Manufacturer="Wurth Elektronik", Power_TotalModule=72mW, Value1=0.072W, Value2=2V
D7: library part CMP-0077511-1, "Diode, Standard Recovery Rectifier, 50 V, 10 A, SMC", Manufacturer="Micro Commercial Components", Value1=10A, Value2=1.2V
